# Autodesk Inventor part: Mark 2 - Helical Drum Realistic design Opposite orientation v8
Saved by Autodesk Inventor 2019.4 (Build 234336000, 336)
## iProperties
Created: 2020-06
Part Number: Mark 2 - Helical Drum Realistic design Opposite orientation v8
Material: Generic
Document SubType Name: Modeling
Designer: Administrator
Density: 1 g/cm^3
Appearance: Default
Author: Administrator
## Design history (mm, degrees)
feature "Body1"
body "Solid1"
